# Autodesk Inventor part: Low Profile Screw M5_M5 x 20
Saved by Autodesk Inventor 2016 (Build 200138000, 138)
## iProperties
Created: 2015-11
Part Number: Low Profile Screw M5_M5 x 20
Material: Generic
Document SubType Name: Modeling
Designer: John
Density: 1 g/cm^3
Appearance: Default
Author: John
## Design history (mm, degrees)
feature "SOLID1"
body "Solid1"
